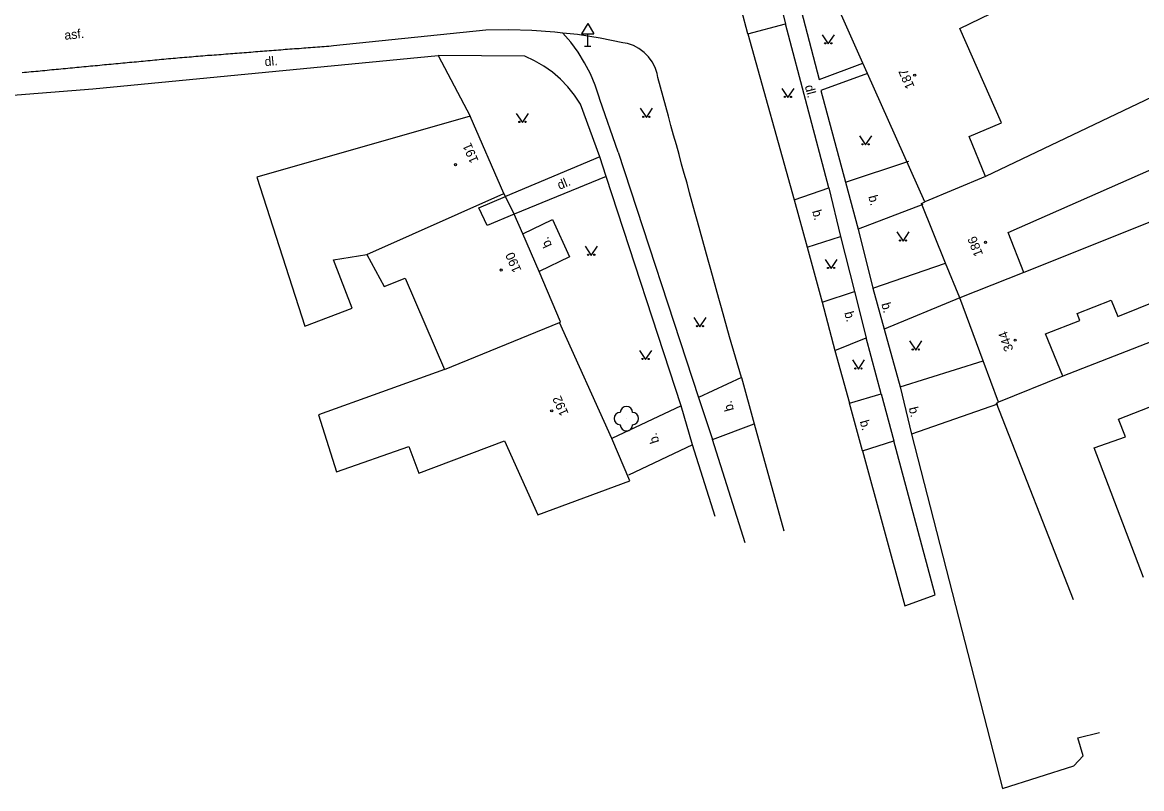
# Model space of a CAD drawing. Extents: x -536391 to -535419, y -1201788 to -1200779.
# Drawn here: x -535590.1 to -535498.7, y -1201665.1 to -1201602.5 of the extents above; entities that cross this region are included whole.
import ezdxf

# ---------------------------------------------------------------- set-up
doc = ezdxf.new("R2010")
doc.units = 0
for name, color, linetype in [('CIZÍ_NADZEM_POPIS', 7, 'Continuous'), ('CIZÍ_PODZEM', 7, 'Continuous'), ('CIZÍ_PODZEM_POPIS', 7, 'Continuous'), ('KONEC_VEDENÍ', 7, 'Continuous'), ('POL_ZNAČKA_PRACOVNÍ', 7, 'Continuous'), ('SDEL_EON', 7, 'Continuous'), ('SDEL_EON_POPIS', 7, 'Continuous'), ('TECH_OCHR_PÁSMO_HRAN', 7, 'Continuous'), ('ZP_EON', 7, 'Continuous')]:
    doc.layers.add(name, color=color, linetype=linetype)

msp = doc.modelspace()

# ---------------------------------------------------------------- linework, layer by layer
at = {"layer": 'CIZÍ_PODZEM'}
for centre in [(-535517.21, -1201606.84), (-535554.71, -1201614.15), (-535511.43, -1201620.49), (-535550.98, -1201622.76), (-535509, -1201628.48), (-535546.85, -1201634.26)]:
    msp.add_circle(centre, 0.0875, dxfattribs=at)
at = {"layer": 'CIZÍ_PODZEM_POPIS'}
for p, q in [((-535543.91, -1201602.614), (-535544.41, -1201603.48)), ((-535543.91, -1201602.614), (-535543.41, -1201603.48)), ((-535544.41, -1201603.48), (-535543.41, -1201603.48)), ((-535543.91, -1201604.48), (-535543.91, -1201603.48)), ((-535544.16, -1201604.48), (-535543.66, -1201604.48))]:
    msp.add_line(p, q, dxfattribs=at)
for points in [[(-535592.23, -1201608.58), (-535584.33, -1201607.95), (-535556.13, -1201605.24)], [(-535556.13, -1201605.24), (-535553.51, -1201610.19)]]:
    msp.add_lwpolyline(points, dxfattribs=at)
at = {"layer": 'KONEC_VEDENÍ'}
msp.add_circle((-535540.75, -1201634.89), 0.0005, dxfattribs=at)
for centre, start, end in [((-535541.25, -1201634.89), 89.99999, 269.99999), ((-535540.75, -1201634.39), 0, 179.99999), ((-535540.25, -1201634.89), 270, 89.99999), ((-535540.75, -1201635.39), 179.99999, 359.99999)]:
    msp.add_arc(centre, 0.5, start, end, dxfattribs=at)
at = {"layer": 'SDEL_EON'}
for points in [[(-535524.76, -1201603.54), (-535524.26, -1201604.29), (-535523.76, -1201603.54)], [(-535528.06, -1201607.92), (-535527.56, -1201608.67), (-535527.06, -1201607.92)], [(-535549.74, -1201609.96), (-535549.24, -1201610.71), (-535548.74, -1201609.96)], [(-535539.62, -1201609.55), (-535539.12, -1201610.3), (-535538.62, -1201609.55)], [(-535521.72, -1201611.79), (-535521.22, -1201612.54), (-535520.72, -1201611.79)], [(-535518.66, -1201619.65), (-535518.16, -1201620.4), (-535517.66, -1201619.65)], [(-535544.12, -1201620.81), (-535543.62, -1201621.56), (-535543.12, -1201620.81)], [(-535524.53, -1201621.89), (-535524.03, -1201622.64), (-535523.53, -1201621.89)], [(-535535.24, -1201626.64), (-535534.74, -1201627.39), (-535534.24, -1201626.64)], [(-535517.62, -1201628.55), (-535517.12, -1201629.3), (-535516.62, -1201628.55)], [(-535539.68, -1201629.32), (-535539.18, -1201630.07), (-535538.68, -1201629.32)], [(-535522.3, -1201630.1), (-535521.8, -1201630.85), (-535521.3, -1201630.1)]]:
    msp.add_lwpolyline(points, dxfattribs=at)
for centre in [(-535524.51, -1201604.24), (-535524.01, -1201604.24), (-535527.81, -1201608.62), (-535527.31, -1201608.62), (-535549.49, -1201610.66), (-535548.99, -1201610.66), (-535539.37, -1201610.25), (-535538.87, -1201610.25), (-535521.47, -1201612.49), (-535520.97, -1201612.49), (-535518.41, -1201620.35), (-535517.91, -1201620.35), (-535543.87, -1201621.51), (-535543.37, -1201621.51), (-535524.28, -1201622.59), (-535523.78, -1201622.59), (-535534.99, -1201627.34), (-535534.49, -1201627.34), (-535517.37, -1201629.25), (-535516.87, -1201629.25), (-535539.43, -1201630.02), (-535538.93, -1201630.02), (-535522.05, -1201630.8), (-535521.55, -1201630.8)]:
    msp.add_circle(centre, 0.05, dxfattribs=at)
at = {"layer": 'SDEL_EON_POPIS'}
for points in [[(-535516.38, -1201617.2), (-535521.06, -1201606.7), (-535521.43, -1201605.87), (-535523.18, -1201601.94)], [(-535553.51, -1201610.19), (-535570.93, -1201615.18)], [(-535550.76, -1201616.51), (-535553.51, -1201610.19)], [(-535549.91, -1201618.2), (-535552.12, -1201619.12), (-535552.8, -1201617.68), (-535550.61, -1201616.74)], [(-535550.61, -1201616.74), (-535550.76, -1201616.51)], [(-535549.91, -1201618.2), (-535550.61, -1201616.74)], [(-535513.53, -1201625.03), (-535514.68, -1201622.21), (-535516.66, -1201617.32), (-535516.38, -1201617.2)], [(-535546.2, -1201627.04), (-535546.14, -1201627), (-535547.86, -1201622.88), (-535549.21, -1201619.8), (-535549.91, -1201618.2)], [(-535510.36, -1201633.56), (-535511.63, -1201630.16), (-535513.53, -1201625.03)], [(-535540.48, -1201639.96), (-535541.93, -1201636.51), (-535546.2, -1201627.04)], [(-535504.24, -1201649.68), (-535510.54, -1201633.63), (-535510.36, -1201633.56)]]:
    msp.add_lwpolyline(points, dxfattribs=at)
at = {"layer": 'TECH_OCHR_PÁSMO_HRAN'}
for points in [[(-535530.74, -1201585.15), (-535525.02, -1201607.19), (-535521.43, -1201605.87)], [(-535528.76, -1201598.67), (-535527.76, -1201602.65)], [(-535530.83, -1201603.48), (-535531.87, -1201599.53)], [(-535530.83, -1201603.48), (-535527.76, -1201602.65)], [(-535524.22, -1201616.04), (-535527.76, -1201602.65)], [(-535545.95, -1201603.4), (-535546.6, -1201603.33), (-535548.48, -1201603.2), (-535550.35, -1201603.15), (-535552.23, -1201603.18), (-535564.67, -1201604.46), (-535564.86, -1201604.48), (-535565.04, -1201604.49), (-535565.23, -1201604.5), (-535565.42, -1201604.52), (-535565.61, -1201604.53), (-535565.79, -1201604.55), (-535565.98, -1201604.56), (-535566.17, -1201604.58), (-535566.36, -1201604.59), (-535566.54, -1201604.6), (-535566.73, -1201604.62), (-535566.92, -1201604.63), (-535567.1, -1201604.65), (-535567.29, -1201604.66), (-535567.48, -1201604.68), (-535567.67, -1201604.69), (-535567.85, -1201604.7), (-535568.04, -1201604.72), (-535568.23, -1201604.73), (-535568.41, -1201604.75), (-535568.6, -1201604.76), (-535568.79, -1201604.77), (-535568.98, -1201604.79), (-535569.16, -1201604.8), (-535569.35, -1201604.82), (-535569.54, -1201604.83), (-535569.72, -1201604.85), (-535569.91, -1201604.86), (-535570.1, -1201604.88), (-535570.29, -1201604.89), (-535570.47, -1201604.91), (-535570.66, -1201604.92), (-535570.85, -1201604.93), (-535571.03, -1201604.95), (-535571.22, -1201604.96), (-535571.41, -1201604.98), (-535571.59, -1201604.99), (-535571.78, -1201605.01), (-535571.97, -1201605.02), (-535572.16, -1201605.04), (-535572.34, -1201605.05), (-535572.53, -1201605.07), (-535572.72, -1201605.08), (-535572.9, -1201605.09), (-535573.09, -1201605.11), (-535573.28, -1201605.12), (-535573.47, -1201605.14), (-535573.65, -1201605.15), (-535573.84, -1201605.17), (-535574.03, -1201605.18), (-535574.21, -1201605.2), (-535574.4, -1201605.21), (-535574.59, -1201605.23), (-535574.78, -1201605.24), (-535574.96, -1201605.25), (-535575.15, -1201605.27), (-535575.34, -1201605.28), (-535575.52, -1201605.3), (-535575.71, -1201605.32), (-535575.9, -1201605.33), (-535576.09, -1201605.34), (-535576.27, -1201605.36), (-535576.46, -1201605.37), (-535576.65, -1201605.39), (-535576.83, -1201605.4), (-535577.02, -1201605.42), (-535577.21, -1201605.43), (-535577.4, -1201605.45), (-535577.58, -1201605.47), (-535577.77, -1201605.49), (-535577.95, -1201605.5), (-535578.14, -1201605.52), (-535578.33, -1201605.54), (-535578.52, -1201605.56), (-535578.7, -1201605.57), (-535578.89, -1201605.59), (-535579.08, -1201605.61), (-535579.26, -1201605.63), (-535579.45, -1201605.64), (-535579.64, -1201605.66), (-535579.82, -1201605.68), (-535580.01, -1201605.7), (-535580.2, -1201605.72), (-535580.38, -1201605.73), (-535580.57, -1201605.75), (-535580.76, -1201605.77), (-535580.94, -1201605.79), (-535581.13, -1201605.8), (-535581.32, -1201605.82), (-535581.51, -1201605.84), (-535581.69, -1201605.86), (-535581.88, -1201605.87), (-535582.07, -1201605.89), (-535582.25, -1201605.91), (-535582.44, -1201605.93)], [(-535533.41, -1201624.29), (-535533.63, -1201623.5), (-535533.85, -1201622.72), (-535534.07, -1201621.94), (-535534.28, -1201621.15), (-535534.5, -1201620.37), (-535534.72, -1201619.58), (-535534.93, -1201618.8), (-535535.15, -1201618.02), (-535535.37, -1201617.23), (-535535.59, -1201616.45), (-535535.8, -1201615.67), (-535536.02, -1201614.88), (-535536.24, -1201614.1), (-535536.45, -1201613.31), (-535536.67, -1201612.53), (-535536.89, -1201611.75), (-535537.11, -1201610.96), (-535537.32, -1201610.18), (-535537.54, -1201609.4), (-535537.76, -1201608.61), (-535538.19, -1201607.04), (-535538.25, -1201606.71), (-535538.41, -1201606.22), (-535538.65, -1201605.76), (-535538.95, -1201605.34), (-535539.31, -1201604.98), (-535539.73, -1201604.67), (-535540.18, -1201604.43), (-535540.67, -1201604.27), (-535541.04, -1201604.19), (-535542.88, -1201603.82), (-535544.74, -1201603.53), (-535545.95, -1201603.4)], [(-535541.42, -1201613.13), (-535542.92, -1201608.83), (-535542.98, -1201608.63), (-535543.3, -1201607.67), (-535543.69, -1201606.73), (-535544.16, -1201605.83), (-535544.69, -1201604.97), (-535545.3, -1201604.16), (-535545.95, -1201603.4)], [(-535530.83, -1201603.48), (-535527.05, -1201617.02)], [(-535542.91, -1201613.52), (-535544.5, -1201609.21), (-535544.98, -1201608.48), (-535545.52, -1201607.8), (-535546.13, -1201607.17), (-535546.79, -1201606.6), (-535547.5, -1201606.1), (-535548.25, -1201605.66), (-535549.04, -1201605.29), (-535556.13, -1201605.24)], [(-535582.44, -1201605.93), (-535582.63, -1201605.95), (-535582.81, -1201605.96), (-535583, -1201605.98), (-535583.19, -1201606), (-535583.37, -1201606.01), (-535583.56, -1201606.03), (-535583.75, -1201606.05), (-535583.93, -1201606.07), (-535584.12, -1201606.09), (-535584.31, -1201606.1), (-535584.5, -1201606.12), (-535584.68, -1201606.14), (-535584.87, -1201606.16), (-535585.06, -1201606.17), (-535585.24, -1201606.19), (-535585.43, -1201606.21), (-535585.62, -1201606.23), (-535585.8, -1201606.25), (-535585.99, -1201606.26), (-535586.18, -1201606.28), (-535586.36, -1201606.3), (-535586.55, -1201606.32), (-535586.74, -1201606.33), (-535586.92, -1201606.35), (-535587.11, -1201606.37), (-535587.3, -1201606.39), (-535587.48, -1201606.4), (-535587.67, -1201606.42), (-535587.86, -1201606.44), (-535588.04, -1201606.46), (-535588.23, -1201606.48), (-535588.42, -1201606.49), (-535588.61, -1201606.51), (-535588.79, -1201606.53), (-535588.98, -1201606.55), (-535589.17, -1201606.56), (-535589.35, -1201606.58), (-535589.54, -1201606.6), (-535589.73, -1201606.62), (-535589.91, -1201606.63), (-535590.1, -1201606.65)], [(-535521.06, -1201606.7), (-535524.87, -1201608.1), (-535522.85, -1201615.58), (-535517.7, -1201613.86)], [(-535542.91, -1201613.52), (-535550.61, -1201616.74)], [(-535542.41, -1201615.11), (-535542.91, -1201613.52)], [(-535541.42, -1201613.13), (-535534.86, -1201633.17)], [(-535542.41, -1201615.11), (-535549.91, -1201618.2)], [(-535536.29, -1201633.84), (-535542.41, -1201615.11)], [(-535522.85, -1201615.58), (-535521.82, -1201619.42)], [(-535527.05, -1201617.02), (-535524.22, -1201616.04)], [(-535524.22, -1201616.04), (-535523.27, -1201620.02)], [(-535527.05, -1201617.02), (-535525.99, -1201620.9)], [(-535516.55, -1201617.4), (-535521.82, -1201619.42)], [(-535549.21, -1201619.8), (-535546.79, -1201618.64), (-535545.39, -1201621.69), (-535547.86, -1201622.88)], [(-535525.99, -1201620.9), (-535523.27, -1201620.02)], [(-535523.27, -1201620.02), (-535522.12, -1201624.5)], [(-535521.82, -1201619.42), (-535520.62, -1201624.25), (-535514.68, -1201622.21)], [(-535525.99, -1201620.9), (-535524.75, -1201625.39)], [(-535531.34, -1201631.54), (-535532.33, -1201628.21), (-535532.55, -1201627.42), (-535532.76, -1201626.64), (-535532.98, -1201625.85), (-535533.2, -1201625.07), (-535533.41, -1201624.29)], [(-535524.75, -1201625.39), (-535522.12, -1201624.5)], [(-535522.12, -1201624.5), (-535521.16, -1201628.3)], [(-535520.62, -1201624.25), (-535519.71, -1201627.6)], [(-535524.75, -1201625.39), (-535523.74, -1201629.32)], [(-535513.53, -1201625.03), (-535519.71, -1201627.6), (-535518.4, -1201632.31), (-535511.63, -1201630.16)], [(-535523.74, -1201629.32), (-535521.16, -1201628.3)], [(-535522.53, -1201633.64), (-535519.95, -1201632.86), (-535521.16, -1201628.3)], [(-535523.74, -1201629.32), (-535522.53, -1201633.64)], [(-535531.34, -1201631.54), (-535534.86, -1201633.17)], [(-535531.34, -1201631.54), (-535530.32, -1201635.31)], [(-535519.95, -1201632.86), (-535518.91, -1201636.72)], [(-535518.4, -1201632.31), (-535517.48, -1201636.17)], [(-535536.29, -1201633.84), (-535541.93, -1201636.51)], [(-535535.34, -1201637.04), (-535536.29, -1201633.84)], [(-535534.86, -1201633.17), (-535533.73, -1201636.6)], [(-535521.47, -1201637.53), (-535522.53, -1201633.64)], [(-535510.45, -1201633.72), (-535517.48, -1201636.17), (-535510.05, -1201665.11), (-535504.22, -1201663.25), (-535503.45, -1201662.44), (-535503.89, -1201660.96), (-535502.11, -1201660.54)], [(-535533.73, -1201636.6), (-535530.32, -1201635.31)], [(-535530.32, -1201635.31), (-535527.9, -1201644.06)], [(-535531.05, -1201645.04), (-535533.73, -1201636.6)], [(-535535.34, -1201637.04), (-535540.59, -1201639.52)], [(-535533.49, -1201642.88), (-535535.34, -1201637.04)], [(-535521.47, -1201637.53), (-535518.91, -1201636.72)], [(-535521.47, -1201637.53), (-535518, -1201650.17)], [(-535518, -1201650.17), (-535515.54, -1201649.28), (-535518.91, -1201636.72)]]:
    msp.add_lwpolyline(points, dxfattribs=at)
at = {"layer": 'ZP_EON'}
for points in [[(-535511.42, -1201615.11), (-535512.76, -1201611.86), (-535510.13, -1201610.73), (-535513.53, -1201603.02), (-535501.82, -1201597.33), (-535501.47, -1201598.07), (-535500.97, -1201597.79), (-535502.17, -1201595.2), (-535503.72, -1201591.89), (-535522.9, -1201601.79)], [(-535508.29, -1201622.96), (-535509.57, -1201619.7), (-535497.15, -1201614.22), (-535497.36, -1201613.69), (-535491.66, -1201611.18), (-535493.68, -1201606.66), (-535511.42, -1201615.11), (-535516.38, -1201617.2)], [(-535505.12, -1201631.43), (-535506.53, -1201627.98), (-535503.73, -1201626.88), (-535503.95, -1201626.32), (-535501.16, -1201625.22), (-535500.63, -1201626.56), (-535492.18, -1201623.16), (-535492.7, -1201621.86), (-535491.84, -1201621.47), (-535492.19, -1201620.68), (-535480.05, -1201614.49), (-535476.82, -1201612.92), (-535479.05, -1201608.98), (-535482.17, -1201610.77), (-535494.6, -1201617.48), (-535508.29, -1201622.96), (-535513.53, -1201625.03)], [(-535570.93, -1201615.18), (-535567, -1201627.35), (-535563.15, -1201625.88), (-535564.66, -1201621.92), (-535561.95, -1201621.48), (-535550.76, -1201616.51)], [(-535561.95, -1201621.48), (-535560.53, -1201624.09), (-535558.82, -1201623.43), (-535555.6, -1201630.89), (-535546.2, -1201627.04)], [(-535498.53, -1201647.88), (-535502.55, -1201637.28), (-535499.99, -1201636.39), (-535500.56, -1201634.94), (-535486.94, -1201629.59), (-535488.98, -1201625.15), (-535505.12, -1201631.43), (-535510.36, -1201633.56)], [(-535555.6, -1201630.89), (-535565.88, -1201634.58), (-535564.42, -1201639.23), (-535558.52, -1201637.16), (-535557.71, -1201639.34), (-535550.71, -1201636.72), (-535547.98, -1201642.76), (-535540.48, -1201639.96)]]:
    msp.add_lwpolyline(points, dxfattribs=at)

# ---------------------------------------------------------------- texts
at = {"layer": 'CIZÍ_NADZEM_POPIS'}
for s, rotation, p in [('187', 113.56998, (-535517.2, -1201607.77)), ('191', 113.52001, (-535552.8, -1201613.83)), ('186', 111.51999, (-535511.61, -1201621.48)), ('190', 113.41997, (-535549.31, -1201622.76)), ('344', 109.67999, (-535509.13, -1201629.26)), ('192', 114.07, (-535545.45, -1201634.47))]:
    msp.add_text(s, height=0.75, rotation=rotation, dxfattribs=at).set_placement(p)
at = {"layer": 'POL_ZNAČKA_PRACOVNÍ'}
for s, rotation, p in [('asf.', 5.87001, (-535586.61, -1201603.96)), ('dl.', 5.49002, (-535570.26, -1201606.12)), ('dl.', 284.80999, (-535526.19, -1201607.74)), ('dl.', 22.38999, (-535546.21, -1201616.21)), ('b.', 285.01001, (-535521, -1201616.75)), ('b.', 285.27998, (-535525.59, -1201617.95)), ('b.', 114.66003, (-535546.81, -1201620.74)), ('b.', 285.2, (-535519.94, -1201625.52)), ('b.', 284.41, (-535522.96, -1201626.24)), ('b.', 105.13999, (-535531.96, -1201634.18)), ('b.', 283.41002, (-535517.7, -1201634.02)), ('b.', 285.23999, (-535521.7, -1201635.12)), ('b.', 107.70999, (-535538.05, -1201636.79))]:
    msp.add_text(s, height=0.75, rotation=rotation, dxfattribs=at).set_placement(p)

doc.saveas('drawing.dxf')
